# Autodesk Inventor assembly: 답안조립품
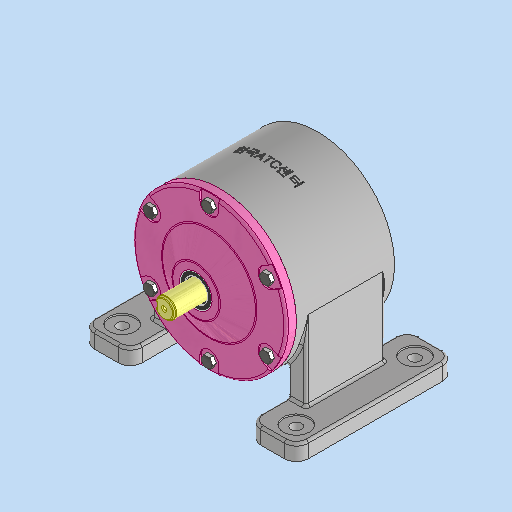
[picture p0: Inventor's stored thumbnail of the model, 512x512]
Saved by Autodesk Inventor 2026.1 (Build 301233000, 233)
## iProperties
Created: 2025-12
Part Number: 답안조립품
Document SubType Name: Assembly
Designer: PC-30
Author: PC-30
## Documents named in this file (17)
- C:\Users\PC-30\Desktop\751203V1014\답안조립품.iam
- C:\Users\PC-30\Desktop\751203V1014\본체.ipt
- C:\Users\PC-30\Desktop\751203V1014\깊은 홈 볼 베어링 6004.ipt
- C:\Users\PC-30\Desktop\751203V1014\기어 축.ipt
- C:\Users\PC-30\Desktop\751203V1014\출력 축.ipt
- C:\Users\PC-30\Desktop\751203V1014\칼라 2.ipt
- C:\Users\PC-30\Desktop\751203V1014\평행 키 6x6x16.ipt
- C:\Users\PC-30\Desktop\751203V1014\종동 기어.ipt
- C:\Users\PC-30\Desktop\751203V1014\구동 기어.ipt
- C:\Users\PC-30\Desktop\751203V1014\칼라 1.ipt
- C:\Users\PC-30\Desktop\751203V1014\엔드 캡.ipt
- C:\Users\PC-30\Desktop\751203V1014\C형 멈춤링 구멍용 42.ipt
- C:\Users\PC-30\Desktop\751203V1014\커버.ipt
- C:\Users\PC-30\Desktop\751203V1014\오일 실 25 40 8.ipt
- C:\Users\PC-30\Desktop\751203V1014\깊은 홈 볼 베어링 6005.ipt
- C:\Users\PC-30\Desktop\751203V1014\6각 머리 볼트 M8x20.ipt
- C:\Users\PC-30\Desktop\751203V1014\6각 구멍붙이 볼트 M4x10.ipt
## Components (9 placed, 4 different names)
1. 구동 기어:1
2. C형 멈춤링 구멍용 42:1
3. 6각 구멍붙이 볼트 M4x10:1
4. 6각 머리 볼트 M8x20:1
5. 6각 머리 볼트 M8x20:2
6. 6각 머리 볼트 M8x20:3
7. 6각 머리 볼트 M8x20:4
8. 6각 머리 볼트 M8x20:5
9. 6각 머리 볼트 M8x20:6
